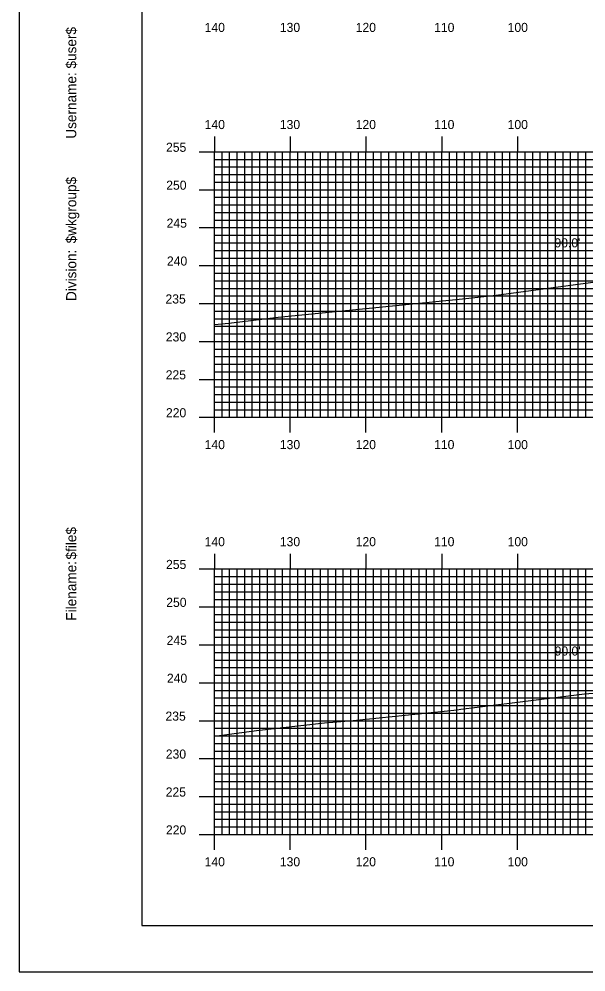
# Model space of a CAD drawing. Extents: x 1817670 to 1818013, y 442591 to 442811.
# Drawn here: x 1817669.8 to 1817744.6, y 442590.5 to 442716.2 of the extents above; entities that cross this region are included whole.
import ezdxf

# ---------------------------------------------------------------- set-up
doc = ezdxf.new("R2010")
doc.units = 0
for name, color, linetype in [('BORDER', 7, 'Continuous'), ('D_Text_Standard', 7, 'Continuous'), ('H_V ANNOTATION', 7, 'Continuous'), ('MAJOR', 7, 'Continuous'), ('MINOR', 7, 'Continuous'), ('PLOT BOUNDARY', 7, 'Continuous'), ('S_Roadway_Centerline', 7, 'Continuous')]:
    doc.layers.add(name, color=color, linetype=linetype)

msp = doc.modelspace()

# ---------------------------------------------------------------- linework, layer by layer
at = {"layer": 'BORDER'}
msp.add_lwpolyline([(1817686.01, 442596.67), (1818006.01, 442596.67), (1818006.01, 442806.67), (1817686.01, 442806.67)], close=True, dxfattribs=at)
at = {"layer": 'MAJOR'}
for p, q in [((1817695.61, 442700.67), (1817695.61, 442698.67)), ((1817705.61, 442700.67), (1817705.61, 442698.67)), ((1817715.61, 442700.67), (1817715.61, 442698.67)), ((1817725.61, 442700.67), (1817725.61, 442698.67)), ((1817735.61, 442700.67), (1817735.61, 442698.67)), ((1817693.61, 442698.67), (1817695.61, 442698.67)), ((1817695.61, 442698.67), (1817975.61, 442698.67)), ((1817695.61, 442663.67), (1817695.61, 442698.67)), ((1817695.61, 442663.67), (1817695.61, 442698.67)), ((1817695.61, 442698.67), (1817975.61, 442698.67)), ((1817705.61, 442663.67), (1817705.61, 442698.67)), ((1817715.61, 442663.67), (1817715.61, 442698.67)), ((1817725.61, 442663.67), (1817725.61, 442698.67)), ((1817735.61, 442663.67), (1817735.61, 442698.67)), ((1817693.61, 442693.67), (1817695.61, 442693.67)), ((1817695.61, 442693.67), (1817975.61, 442693.67)), ((1817693.61, 442688.67), (1817695.61, 442688.67)), ((1817695.61, 442688.67), (1817975.61, 442688.67)), ((1817693.61, 442683.67), (1817695.61, 442683.67)), ((1817695.61, 442683.67), (1817975.61, 442683.67)), ((1817693.61, 442678.67), (1817695.61, 442678.67)), ((1817695.61, 442678.67), (1817975.61, 442678.67)), ((1817693.61, 442673.67), (1817695.61, 442673.67)), ((1817695.61, 442673.67), (1817975.61, 442673.67)), ((1817693.61, 442668.67), (1817695.61, 442668.67)), ((1817695.61, 442668.67), (1817975.61, 442668.67)), ((1817693.61, 442663.67), (1817695.61, 442663.67)), ((1817695.61, 442663.67), (1817975.61, 442663.67)), ((1817695.61, 442663.67), (1817975.61, 442663.67)), ((1817695.61, 442661.66), (1817695.61, 442663.67)), ((1817705.61, 442661.66), (1817705.61, 442663.67)), ((1817715.61, 442661.66), (1817715.61, 442663.67)), ((1817725.61, 442661.66), (1817725.61, 442663.67)), ((1817735.61, 442661.66), (1817735.61, 442663.67)), ((1817695.61, 442645.67), (1817695.61, 442643.67)), ((1817705.61, 442645.67), (1817705.61, 442643.67)), ((1817715.61, 442645.67), (1817715.61, 442643.67)), ((1817725.61, 442645.67), (1817725.61, 442643.67)), ((1817735.61, 442645.67), (1817735.61, 442643.67)), ((1817693.61, 442643.67), (1817695.61, 442643.67)), ((1817695.61, 442643.67), (1817975.61, 442643.67)), ((1817695.61, 442608.67), (1817695.61, 442643.67)), ((1817695.61, 442608.67), (1817695.61, 442643.67)), ((1817695.61, 442643.67), (1817975.61, 442643.67)), ((1817705.61, 442608.67), (1817705.61, 442643.67)), ((1817715.61, 442608.67), (1817715.61, 442643.67)), ((1817725.61, 442608.67), (1817725.61, 442643.67)), ((1817735.61, 442608.67), (1817735.61, 442643.67)), ((1817693.61, 442638.67), (1817695.61, 442638.67)), ((1817695.61, 442638.67), (1817975.61, 442638.67)), ((1817693.61, 442633.67), (1817695.61, 442633.67)), ((1817695.61, 442633.67), (1817975.61, 442633.67)), ((1817693.61, 442628.67), (1817695.61, 442628.67)), ((1817695.61, 442628.67), (1817975.61, 442628.67)), ((1817693.61, 442623.67), (1817695.61, 442623.67)), ((1817695.61, 442623.67), (1817975.61, 442623.67)), ((1817693.61, 442618.67), (1817695.61, 442618.67)), ((1817695.61, 442618.67), (1817975.61, 442618.67)), ((1817693.61, 442613.67), (1817695.61, 442613.67)), ((1817695.61, 442613.67), (1817975.61, 442613.67)), ((1817693.61, 442608.67), (1817695.61, 442608.67)), ((1817695.61, 442608.67), (1817975.61, 442608.67)), ((1817695.61, 442608.67), (1817975.61, 442608.67)), ((1817695.61, 442606.66), (1817695.61, 442608.67)), ((1817705.61, 442606.66), (1817705.61, 442608.67)), ((1817715.61, 442606.66), (1817715.61, 442608.67)), ((1817725.61, 442606.66), (1817725.61, 442608.67)), ((1817735.61, 442606.66), (1817735.61, 442608.67))]:
    msp.add_line(p, q, dxfattribs=at)
at = {"layer": 'MINOR'}
for p, q in [((1817696.61, 442663.67), (1817696.61, 442698.67)), ((1817697.61, 442663.67), (1817697.61, 442698.67)), ((1817698.61, 442663.67), (1817698.61, 442698.67)), ((1817699.61, 442663.67), (1817699.61, 442698.67)), ((1817700.61, 442663.67), (1817700.61, 442698.67)), ((1817701.61, 442663.67), (1817701.61, 442698.67)), ((1817702.61, 442663.67), (1817702.61, 442698.67)), ((1817703.61, 442663.67), (1817703.61, 442698.67)), ((1817704.61, 442663.67), (1817704.61, 442698.67)), ((1817706.61, 442663.67), (1817706.61, 442698.67)), ((1817707.61, 442663.67), (1817707.61, 442698.67)), ((1817708.61, 442663.67), (1817708.61, 442698.67)), ((1817709.61, 442663.67), (1817709.61, 442698.67)), ((1817710.61, 442663.67), (1817710.61, 442698.67)), ((1817711.61, 442663.67), (1817711.61, 442698.67)), ((1817712.61, 442663.67), (1817712.61, 442698.67)), ((1817713.61, 442663.67), (1817713.61, 442698.67)), ((1817714.61, 442663.67), (1817714.61, 442698.67)), ((1817716.61, 442663.67), (1817716.61, 442698.67)), ((1817717.61, 442663.67), (1817717.61, 442698.67)), ((1817718.61, 442663.67), (1817718.61, 442698.67)), ((1817719.61, 442663.67), (1817719.61, 442698.67)), ((1817720.61, 442663.67), (1817720.61, 442698.67)), ((1817721.61, 442663.67), (1817721.61, 442698.67)), ((1817722.61, 442663.67), (1817722.61, 442698.67)), ((1817723.61, 442663.67), (1817723.61, 442698.67)), ((1817724.61, 442663.67), (1817724.61, 442698.67)), ((1817726.61, 442663.67), (1817726.61, 442698.67)), ((1817727.61, 442663.67), (1817727.61, 442698.67)), ((1817728.61, 442663.67), (1817728.61, 442698.67)), ((1817729.61, 442663.67), (1817729.61, 442698.67)), ((1817730.61, 442663.67), (1817730.61, 442698.67)), ((1817731.61, 442663.67), (1817731.61, 442698.67)), ((1817732.61, 442663.67), (1817732.61, 442698.67)), ((1817733.61, 442663.67), (1817733.61, 442698.67)), ((1817734.61, 442663.67), (1817734.61, 442698.67)), ((1817736.61, 442663.67), (1817736.61, 442698.67)), ((1817737.61, 442663.67), (1817737.61, 442698.67)), ((1817738.61, 442663.67), (1817738.61, 442698.67)), ((1817739.61, 442663.67), (1817739.61, 442698.67)), ((1817740.61, 442663.67), (1817740.61, 442698.67)), ((1817741.61, 442663.67), (1817741.61, 442698.67)), ((1817742.61, 442663.67), (1817742.61, 442698.67)), ((1817743.61, 442663.67), (1817743.61, 442698.67)), ((1817744.61, 442663.67), (1817744.61, 442698.67)), ((1817695.61, 442697.67), (1817975.61, 442697.67)), ((1817695.61, 442697.67), (1817697.62, 442697.67)), ((1817695.61, 442696.67), (1817975.61, 442696.67)), ((1817695.61, 442696.67), (1817697.62, 442696.67)), ((1817695.61, 442695.67), (1817975.61, 442695.67)), ((1817695.61, 442695.67), (1817697.62, 442695.67)), ((1817695.61, 442694.67), (1817975.61, 442694.67)), ((1817695.61, 442694.67), (1817697.62, 442694.67)), ((1817695.61, 442692.67), (1817975.61, 442692.67)), ((1817695.61, 442692.67), (1817697.62, 442692.67)), ((1817695.61, 442691.67), (1817975.61, 442691.67)), ((1817695.61, 442691.67), (1817697.62, 442691.67)), ((1817695.61, 442690.67), (1817975.61, 442690.67)), ((1817695.61, 442690.67), (1817697.62, 442690.67)), ((1817695.61, 442689.67), (1817975.61, 442689.67)), ((1817695.61, 442689.67), (1817697.62, 442689.67)), ((1817695.61, 442687.67), (1817975.61, 442687.67)), ((1817695.61, 442687.67), (1817697.62, 442687.67)), ((1817695.61, 442686.67), (1817975.61, 442686.67)), ((1817695.61, 442686.67), (1817697.62, 442686.67)), ((1817695.61, 442685.67), (1817975.61, 442685.67)), ((1817695.61, 442685.67), (1817697.62, 442685.67)), ((1817695.61, 442684.67), (1817975.61, 442684.67)), ((1817695.61, 442684.67), (1817697.62, 442684.67)), ((1817695.61, 442682.67), (1817975.61, 442682.67)), ((1817695.61, 442682.67), (1817697.62, 442682.67)), ((1817695.61, 442681.67), (1817975.61, 442681.67)), ((1817695.61, 442681.67), (1817697.62, 442681.67)), ((1817695.61, 442680.67), (1817975.61, 442680.67)), ((1817695.61, 442680.67), (1817697.62, 442680.67)), ((1817695.61, 442679.67), (1817975.61, 442679.67)), ((1817695.61, 442679.67), (1817697.62, 442679.67)), ((1817695.61, 442677.67), (1817975.61, 442677.67)), ((1817695.61, 442677.67), (1817697.62, 442677.67)), ((1817695.61, 442676.67), (1817975.61, 442676.67)), ((1817695.61, 442676.67), (1817697.62, 442676.67)), ((1817695.61, 442675.67), (1817975.61, 442675.67)), ((1817695.61, 442675.67), (1817697.62, 442675.67)), ((1817695.61, 442674.67), (1817975.61, 442674.67)), ((1817695.61, 442674.67), (1817697.62, 442674.67)), ((1817695.61, 442672.67), (1817975.61, 442672.67)), ((1817695.61, 442672.67), (1817697.62, 442672.67)), ((1817695.61, 442671.67), (1817975.61, 442671.67)), ((1817695.61, 442671.67), (1817697.62, 442671.67)), ((1817695.61, 442670.67), (1817975.61, 442670.67)), ((1817695.61, 442670.67), (1817697.62, 442670.67)), ((1817695.61, 442669.67), (1817975.61, 442669.67)), ((1817695.61, 442669.67), (1817697.62, 442669.67)), ((1817695.61, 442667.67), (1817975.61, 442667.67)), ((1817695.61, 442667.67), (1817697.62, 442667.67)), ((1817695.61, 442666.67), (1817975.61, 442666.67)), ((1817695.61, 442666.67), (1817697.62, 442666.67)), ((1817695.61, 442665.67), (1817975.61, 442665.67)), ((1817695.61, 442665.67), (1817697.62, 442665.67)), ((1817695.61, 442664.67), (1817975.61, 442664.67)), ((1817695.61, 442664.67), (1817697.62, 442664.67)), ((1817696.61, 442608.67), (1817696.61, 442643.67)), ((1817697.61, 442608.67), (1817697.61, 442643.67)), ((1817698.61, 442608.67), (1817698.61, 442643.67)), ((1817699.61, 442608.67), (1817699.61, 442643.67)), ((1817700.61, 442608.67), (1817700.61, 442643.67)), ((1817701.61, 442608.67), (1817701.61, 442643.67)), ((1817702.61, 442608.67), (1817702.61, 442643.67)), ((1817703.61, 442608.67), (1817703.61, 442643.67)), ((1817704.61, 442608.67), (1817704.61, 442643.67)), ((1817706.61, 442608.67), (1817706.61, 442643.67)), ((1817707.61, 442608.67), (1817707.61, 442643.67)), ((1817708.61, 442608.67), (1817708.61, 442643.67)), ((1817709.61, 442608.67), (1817709.61, 442643.67)), ((1817710.61, 442608.67), (1817710.61, 442643.67)), ((1817711.61, 442608.67), (1817711.61, 442643.67)), ((1817712.61, 442608.67), (1817712.61, 442643.67)), ((1817713.61, 442608.67), (1817713.61, 442643.67)), ((1817714.61, 442608.67), (1817714.61, 442643.67)), ((1817716.61, 442608.67), (1817716.61, 442643.67)), ((1817717.61, 442608.67), (1817717.61, 442643.67)), ((1817718.61, 442608.67), (1817718.61, 442643.67)), ((1817719.61, 442608.67), (1817719.61, 442643.67)), ((1817720.61, 442608.67), (1817720.61, 442643.67)), ((1817721.61, 442608.67), (1817721.61, 442643.67)), ((1817722.61, 442608.67), (1817722.61, 442643.67)), ((1817723.61, 442608.67), (1817723.61, 442643.67)), ((1817724.61, 442608.67), (1817724.61, 442643.67)), ((1817726.61, 442608.67), (1817726.61, 442643.67)), ((1817727.61, 442608.67), (1817727.61, 442643.67)), ((1817728.61, 442608.67), (1817728.61, 442643.67)), ((1817729.61, 442608.67), (1817729.61, 442643.67)), ((1817730.61, 442608.67), (1817730.61, 442643.67)), ((1817731.61, 442608.67), (1817731.61, 442643.67)), ((1817732.61, 442608.67), (1817732.61, 442643.67)), ((1817733.61, 442608.67), (1817733.61, 442643.67)), ((1817734.61, 442608.67), (1817734.61, 442643.67)), ((1817736.61, 442608.67), (1817736.61, 442643.67)), ((1817737.61, 442608.67), (1817737.61, 442643.67)), ((1817738.61, 442608.67), (1817738.61, 442643.67)), ((1817739.61, 442608.67), (1817739.61, 442643.67)), ((1817740.61, 442608.67), (1817740.61, 442643.67)), ((1817741.61, 442608.67), (1817741.61, 442643.67)), ((1817742.61, 442608.67), (1817742.61, 442643.67)), ((1817743.61, 442608.67), (1817743.61, 442643.67)), ((1817744.61, 442608.67), (1817744.61, 442643.67)), ((1817695.61, 442642.67), (1817975.61, 442642.67)), ((1817695.61, 442642.67), (1817697.62, 442642.67)), ((1817695.61, 442641.67), (1817975.61, 442641.67)), ((1817695.61, 442641.67), (1817697.62, 442641.67)), ((1817695.61, 442640.67), (1817975.61, 442640.67)), ((1817695.61, 442640.67), (1817697.62, 442640.67)), ((1817695.61, 442639.67), (1817975.61, 442639.67)), ((1817695.61, 442639.67), (1817697.62, 442639.67)), ((1817695.61, 442637.67), (1817975.61, 442637.67)), ((1817695.61, 442637.67), (1817697.62, 442637.67)), ((1817695.61, 442636.67), (1817975.61, 442636.67)), ((1817695.61, 442636.67), (1817697.62, 442636.67)), ((1817695.61, 442635.67), (1817975.61, 442635.67)), ((1817695.61, 442635.67), (1817697.62, 442635.67)), ((1817695.61, 442634.67), (1817975.61, 442634.67)), ((1817695.61, 442634.67), (1817697.62, 442634.67)), ((1817695.61, 442632.67), (1817975.61, 442632.67)), ((1817695.61, 442632.67), (1817697.62, 442632.67)), ((1817695.61, 442631.67), (1817975.61, 442631.67)), ((1817695.61, 442631.67), (1817697.62, 442631.67)), ((1817695.61, 442630.67), (1817975.61, 442630.67)), ((1817695.61, 442630.67), (1817697.62, 442630.67)), ((1817695.61, 442629.67), (1817975.61, 442629.67)), ((1817695.61, 442629.67), (1817697.62, 442629.67)), ((1817695.61, 442627.67), (1817975.61, 442627.67)), ((1817695.61, 442627.67), (1817697.62, 442627.67)), ((1817695.61, 442626.67), (1817975.61, 442626.67)), ((1817695.61, 442626.67), (1817697.62, 442626.67)), ((1817695.61, 442625.67), (1817975.61, 442625.67)), ((1817695.61, 442625.67), (1817697.62, 442625.67)), ((1817695.61, 442624.67), (1817975.61, 442624.67)), ((1817695.61, 442624.67), (1817697.62, 442624.67)), ((1817695.61, 442622.67), (1817975.61, 442622.67)), ((1817695.61, 442622.67), (1817697.62, 442622.67)), ((1817695.61, 442621.67), (1817975.61, 442621.67)), ((1817695.61, 442621.67), (1817697.62, 442621.67)), ((1817695.61, 442620.67), (1817975.61, 442620.67)), ((1817695.61, 442620.67), (1817697.62, 442620.67)), ((1817695.61, 442619.67), (1817975.61, 442619.67)), ((1817695.61, 442619.67), (1817697.62, 442619.67)), ((1817695.61, 442617.67), (1817975.61, 442617.67)), ((1817695.61, 442617.67), (1817697.62, 442617.67)), ((1817695.61, 442616.67), (1817975.61, 442616.67)), ((1817695.61, 442616.67), (1817697.62, 442616.67)), ((1817695.61, 442615.67), (1817975.61, 442615.67)), ((1817695.61, 442615.67), (1817697.62, 442615.67)), ((1817695.61, 442614.67), (1817975.61, 442614.67)), ((1817695.61, 442614.67), (1817697.62, 442614.67)), ((1817695.61, 442612.67), (1817975.61, 442612.67)), ((1817695.61, 442612.67), (1817697.62, 442612.67)), ((1817695.61, 442611.67), (1817975.61, 442611.67)), ((1817695.61, 442611.67), (1817697.62, 442611.67)), ((1817695.61, 442610.67), (1817975.61, 442610.67)), ((1817695.61, 442610.67), (1817697.62, 442610.67)), ((1817695.61, 442609.67), (1817975.61, 442609.67)), ((1817695.61, 442609.67), (1817697.62, 442609.67))]:
    msp.add_line(p, q, dxfattribs=at)
at = {"layer": 'PLOT BOUNDARY'}
msp.add_lwpolyline([(1817669.83, 442590.55), (1818009.83, 442590.55), (1818009.83, 442810.55), (1817669.83, 442810.55)], close=True, dxfattribs=at)
at = {"layer": 'S_Roadway_Centerline'}
for points in [[(1817695.61, 442675.89), (1817697.5, 442676.08), (1817704.01, 442676.85), (1817715.14, 442677.95), (1817728.79, 442679.32), (1817731.55, 442679.62), (1817732.78, 442679.75), (1817748.2, 442681.82), (1817755.93, 442682.57), (1817764.76, 442683.38), (1817769.96, 442683.88), (1817782.59, 442684.79), (1817792.39, 442685.49), (1817799.05, 442686), (1817801.45, 442686.16), (1817815.76, 442687.29), (1817824.57, 442687.98), (1817833.37, 442688.54), (1817847.37, 442689.15), (1817850.18, 442689.23), (1817856.46, 442689.49), (1817864.27, 442689.84), (1817866.79, 442689.88)], [(1817695.61, 442621.62), (1817701.14, 442622.37), (1817710.12, 442623.37), (1817713.92, 442623.7), (1817727.64, 442625.1), (1817728.14, 442625.17), (1817730.27, 442625.44), (1817744.46, 442627.2), (1817749.03, 442627.56)]]:
    msp.add_lwpolyline(points, dxfattribs=at)

# ---------------------------------------------------------------- texts
at = {"layer": 'BORDER'}
for s, p in [('$user$', (1817677.38, 442709.65)), ('Username:', (1817677.38, 442700.4)), ('$wkgroup$', (1817677.38, 442686.6)), ('Division:', (1817677.38, 442679)), ('$file$', (1817677.38, 442644.92)), ('Filename:', (1817677.38, 442636.86))]:
    msp.add_text(s, height=1.339, rotation=90, dxfattribs=at).set_placement(p)
at = {"layer": 'D_Text_Standard'}
for p in [(1817740.48, 442686.07), (1817740.5, 442632.26)]:
    msp.add_text("90.0'", height=1.2, dxfattribs=at).set_placement(p)
at = {"layer": 'H_V ANNOTATION'}
for s, p in [('140', (1817694.32, 442714.47)), ('130', (1817704.24, 442714.47)), ('120', (1817714.25, 442714.47)), ('110', (1817724.6, 442714.47)), ('100', (1817734.3, 442714.47)), ('140', (1817694.32, 442701.67)), ('130', (1817704.24, 442701.67)), ('120', (1817714.25, 442701.67)), ('110', (1817724.6, 442701.67)), ('100', (1817734.3, 442701.67)), ('255', (1817689.22, 442698.67)), ('250', (1817689.25, 442693.67)), ('245', (1817689.3, 442688.67)), ('240', (1817689.34, 442683.67)), ('235', (1817689.15, 442678.67)), ('230', (1817689.19, 442673.67)), ('225', (1817689.18, 442668.67)), ('220', (1817689.21, 442663.67)), ('140', (1817694.32, 442659.47)), ('130', (1817704.24, 442659.47)), ('120', (1817714.25, 442659.47)), ('110', (1817724.6, 442659.47)), ('100', (1817734.3, 442659.47)), ('140', (1817694.32, 442646.67)), ('130', (1817704.24, 442646.67)), ('120', (1817714.25, 442646.67)), ('110', (1817724.6, 442646.67)), ('100', (1817734.3, 442646.67)), ('255', (1817689.22, 442643.67)), ('250', (1817689.25, 442638.67)), ('245', (1817689.3, 442633.67)), ('240', (1817689.34, 442628.67)), ('235', (1817689.15, 442623.67)), ('230', (1817689.19, 442618.67)), ('225', (1817689.18, 442613.67)), ('220', (1817689.21, 442608.67)), ('140', (1817694.32, 442604.47)), ('130', (1817704.24, 442604.47)), ('120', (1817714.25, 442604.47)), ('110', (1817724.6, 442604.47)), ('100', (1817734.3, 442604.47))]:
    msp.add_text(s, height=1.2, dxfattribs=at).set_placement(p)
at = {"layer": 'MAJOR'}
for p in [(1817695.6, 442663.67), (1817695.6, 442608.67)]:
    msp.add_text('-', height=0.012, dxfattribs=at).set_placement(p)

doc.saveas('drawing.dxf')
